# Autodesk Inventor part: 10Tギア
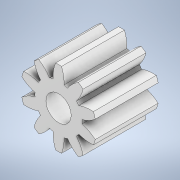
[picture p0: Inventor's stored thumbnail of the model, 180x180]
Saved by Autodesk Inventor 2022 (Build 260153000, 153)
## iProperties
CustomPartVersion: 1
Created: 2024-10
Part Number: 10Tギア
Material: アセタール樹脂、白
Document SubType Name: Modeling
Designer: shimizu
Categories: <?xml version="1.0" encoding="UTF-16"?> <MemberInstance><Categories><FamilyTemplate><FamilyTemplateParameter ValueType="xs:double" Id="1" ObjectReferenceKey="da
Density: 1.425 g/cm^3
Appearance: 滑らか - 白
Author: shimizu
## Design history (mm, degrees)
sketch "Sketch1"
  geometry: C1 r 3 at (0, 0)
  constraints: 1 centre point
  dimensions: "d0" = 6 diameter of C1 (= da_da)
extrude "Extrusion1" new body sketch "Sketch1" distance "d1" = 5 (= da_b); taper "d2" = 0 deg
workplane "Work Plane2"
sketch "Sketch2"
  geometry: C1 r 3 at (0, 0) reference; C2 r 2.5 at (0, 0)
  constraints: 1 centre point, 1 coincident
  dimensions: "d3" = 5 diameter of C2 (= da_d)
feature "ピッチ円直径" sketch "Sketch2" dims "d4" = 10, "d5" = 0
workplane "Work Plane8"
workplane "Work Plane9"
feature "平歯車" dims "da_b" = 5, "da_d" = 5, "da_aw" = 11.75, "da_da" = 6, "da_df" = 3.75, "da_dw" = 5, angle "da_beta" = 0 deg, "da_lefttooth" = 0, "da_righttooth" = 0
sketch "スケッチ3"
  geometry: C1 r 1 at (0, 0); 1 further point
  constraints: 1 centre point, 1 coincident
  dimensions: "d49" = 2 diameter of C1
extrude "押し出し2" cut sketch "スケッチ3" extent not by distance; stored distance "d50" = 0; taper "d51" = 0 deg
sketch "スケッチ4"
  geometry: L1 (0, 3.357)-(0, 0); C1 r 1 at (0, 0) reference; 1 further point
  constraints: 2 end point, 1 vertical
body "Solid1"
body "Srf1"
other parameters: "d16" = 11.75 (= da_aw), "d17" = 0, "d34" = 18 deg (computed from da_z), "d39" = 0, "d41" = 0, "d43" = 11.75 (= da_aw), "d46" = 11.75 (= da_aw), "d47" = 0, "d48" = 0
